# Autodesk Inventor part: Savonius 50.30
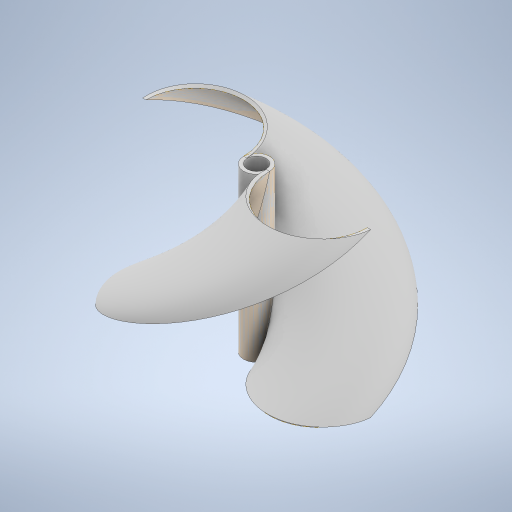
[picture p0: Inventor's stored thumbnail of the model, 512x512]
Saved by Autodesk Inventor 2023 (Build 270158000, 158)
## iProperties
Created: 2025-05
Part Number: Savonius 50.30
Material: Generic
Document SubType Name: Modeling
Designer: Brecht.Carpentier
Density: 1 g/cm^3
Appearance: Default
Author: Brecht.Carpentier
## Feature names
1. Extrusion1
## Parameters: d2 = 25 mm, d3 = 0, d4 = 5.8 mm, d5 = 8 mm, d9 = 0, d12 = 0, d13 = 0, d14 = 1 mm, d15 = 1 mm, d18 = 1 mm, d19 = 1 mm
